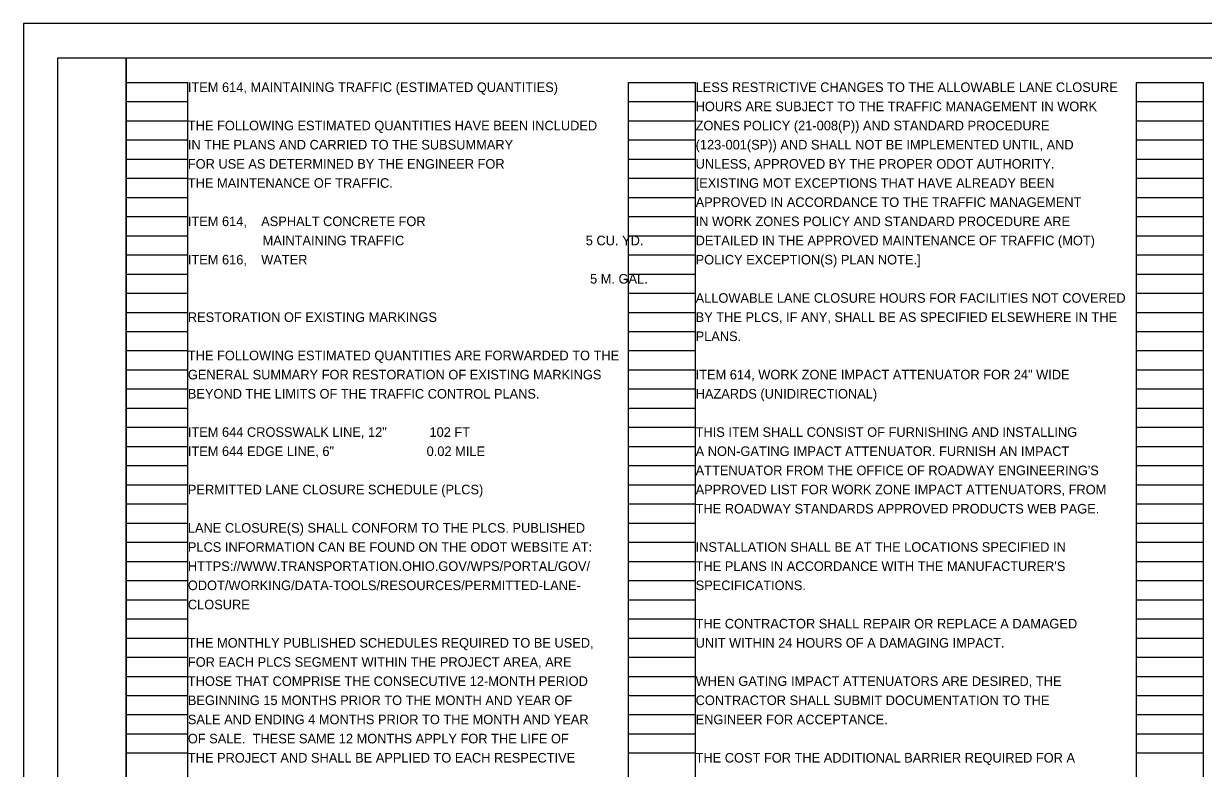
# Model space of a CAD drawing. Extents: x -49.3 to -15.3, y 0 to 22.
# Drawn here: x -49.3 to -32.06, y 11.11 to 22 of the extents above; entities that cross this region are included whole.
import ezdxf

# ---------------------------------------------------------------- set-up
doc = ezdxf.new("R2010")
doc.units = 0
for name, color, linetype in [('SC_Scratch1', 7, 'Continuous'), ('SC_Scratch2', 7, 'Continuous'), ('SH_Text', 7, 'Continuous')]:
    doc.layers.add(name, color=color, linetype=linetype)

msp = doc.modelspace()

# ---------------------------------------------------------------- linework, layer by layer
at = {"layer": 'SC_Scratch1'}
for p, q in [((-47.804, 0.98), (-47.804, 21.14)), ((-47.804, 21.14), (-46.904, 21.14)), ((-46.904, 0.98), (-46.904, 21.14)), ((-40.464, 0.98), (-40.464, 21.14)), ((-40.464, 21.14), (-39.484, 21.14)), ((-39.484, 0.98), (-39.484, 21.14)), ((-33.044, 0.98), (-33.044, 21.14)), ((-33.044, 21.14), (-32.064, 21.14)), ((-32.064, 0.98), (-32.064, 21.14)), ((-47.804, 20.86), (-46.904, 20.86)), ((-40.464, 20.86), (-39.484, 20.86)), ((-33.044, 20.86), (-32.064, 20.86)), ((-47.804, 20.58), (-46.904, 20.58)), ((-40.464, 20.58), (-39.484, 20.58)), ((-33.044, 20.58), (-32.064, 20.58)), ((-47.804, 20.3), (-46.904, 20.3)), ((-40.464, 20.3), (-39.484, 20.3)), ((-33.044, 20.3), (-32.064, 20.3)), ((-47.804, 20.02), (-46.904, 20.02)), ((-40.464, 20.02), (-39.484, 20.02)), ((-33.044, 20.02), (-32.064, 20.02)), ((-47.804, 19.74), (-46.904, 19.74)), ((-40.464, 19.74), (-39.484, 19.74)), ((-33.044, 19.74), (-32.064, 19.74)), ((-47.804, 19.46), (-46.904, 19.46)), ((-40.464, 19.46), (-39.484, 19.46)), ((-33.044, 19.46), (-32.064, 19.46)), ((-47.804, 19.18), (-46.904, 19.18)), ((-40.464, 19.18), (-39.484, 19.18)), ((-33.044, 19.18), (-32.064, 19.18)), ((-47.804, 18.9), (-46.904, 18.9)), ((-40.464, 18.9), (-39.484, 18.9)), ((-33.044, 18.9), (-32.064, 18.9)), ((-47.804, 18.62), (-46.904, 18.62)), ((-40.464, 18.62), (-39.484, 18.62)), ((-33.044, 18.62), (-32.064, 18.62)), ((-47.804, 18.34), (-46.904, 18.34)), ((-40.464, 18.34), (-39.484, 18.34)), ((-33.044, 18.34), (-32.064, 18.34)), ((-47.804, 18.06), (-46.904, 18.06)), ((-40.464, 18.06), (-39.484, 18.06)), ((-33.044, 18.06), (-32.064, 18.06)), ((-47.804, 17.78), (-46.904, 17.78)), ((-40.464, 17.78), (-39.484, 17.78)), ((-33.044, 17.78), (-32.064, 17.78)), ((-47.804, 17.5), (-46.904, 17.5)), ((-40.464, 17.5), (-39.484, 17.5)), ((-33.044, 17.5), (-32.064, 17.5)), ((-47.804, 17.22), (-46.904, 17.22)), ((-40.464, 17.22), (-39.484, 17.22)), ((-33.044, 17.22), (-32.064, 17.22)), ((-47.804, 16.94), (-46.904, 16.94)), ((-40.464, 16.94), (-39.484, 16.94)), ((-33.044, 16.94), (-32.064, 16.94)), ((-47.804, 16.66), (-46.904, 16.66)), ((-40.464, 16.66), (-39.484, 16.66)), ((-33.044, 16.66), (-32.064, 16.66)), ((-47.804, 16.38), (-46.904, 16.38)), ((-40.464, 16.38), (-39.484, 16.38)), ((-33.044, 16.38), (-32.064, 16.38)), ((-47.804, 16.1), (-46.904, 16.1)), ((-40.464, 16.1), (-39.484, 16.1)), ((-33.044, 16.1), (-32.064, 16.1)), ((-47.804, 15.82), (-46.904, 15.82)), ((-40.464, 15.82), (-39.484, 15.82)), ((-33.044, 15.82), (-32.064, 15.82)), ((-47.804, 15.54), (-46.904, 15.54)), ((-40.464, 15.54), (-39.484, 15.54)), ((-33.044, 15.54), (-32.064, 15.54)), ((-47.804, 15.26), (-46.904, 15.26)), ((-40.464, 15.26), (-39.484, 15.26)), ((-33.044, 15.26), (-32.064, 15.26)), ((-47.804, 14.98), (-46.904, 14.98)), ((-40.464, 14.98), (-39.484, 14.98)), ((-33.044, 14.98), (-32.064, 14.98)), ((-47.804, 14.7), (-46.904, 14.7)), ((-40.464, 14.7), (-39.484, 14.7)), ((-33.044, 14.7), (-32.064, 14.7)), ((-47.804, 14.42), (-46.904, 14.42)), ((-40.464, 14.42), (-39.484, 14.42)), ((-33.044, 14.42), (-32.064, 14.42)), ((-47.804, 14.14), (-46.904, 14.14)), ((-40.464, 14.14), (-39.484, 14.14)), ((-33.044, 14.14), (-32.064, 14.14)), ((-47.804, 13.86), (-46.904, 13.86)), ((-40.464, 13.86), (-39.484, 13.86)), ((-33.044, 13.86), (-32.064, 13.86)), ((-47.804, 13.58), (-46.904, 13.58)), ((-40.464, 13.58), (-39.484, 13.58)), ((-33.044, 13.58), (-32.064, 13.58)), ((-47.804, 13.3), (-46.904, 13.3)), ((-40.464, 13.3), (-39.484, 13.3)), ((-33.044, 13.3), (-32.064, 13.3)), ((-47.804, 13.02), (-46.904, 13.02)), ((-40.464, 13.02), (-39.484, 13.02)), ((-33.044, 13.02), (-32.064, 13.02)), ((-47.804, 12.74), (-46.904, 12.74)), ((-40.464, 12.74), (-39.484, 12.74)), ((-33.044, 12.74), (-32.064, 12.74)), ((-47.804, 12.46), (-46.904, 12.46)), ((-40.464, 12.46), (-39.484, 12.46)), ((-33.044, 12.46), (-32.064, 12.46)), ((-47.804, 12.18), (-46.904, 12.18)), ((-40.464, 12.18), (-39.484, 12.18)), ((-33.044, 12.18), (-32.064, 12.18)), ((-47.804, 11.9), (-46.904, 11.9)), ((-40.464, 11.9), (-39.484, 11.9)), ((-33.044, 11.9), (-32.064, 11.9)), ((-47.804, 11.62), (-46.904, 11.62)), ((-40.464, 11.62), (-39.484, 11.62)), ((-33.044, 11.62), (-32.064, 11.62)), ((-47.804, 11.34), (-46.904, 11.34)), ((-40.464, 11.34), (-39.484, 11.34)), ((-33.044, 11.34), (-32.064, 11.34))]:
    msp.add_line(p, q, dxfattribs=at)
at = {"layer": 'SC_Scratch2'}
for points in [[(-49.304, 0), (-15.304, 0), (-15.304, 22), (-49.304, 22)], [(-48.804, 21.5), (-47.804, 21.5), (-47.804, 0.5), (-48.804, 0.5)], [(-47.804, 21.5), (-15.804, 21.5), (-15.804, 0.5), (-47.804, 0.5)]]:
    msp.add_lwpolyline(points, close=True, dxfattribs=at)

# ---------------------------------------------------------------- texts
at = {"layer": 'SH_Text'}
for s, p in [('ITEM 614, MAINTAINING TRAFFIC (ESTIMATED QUANTITIES)', (-46.904, 21)), ('LESS RESTRICTIVE CHANGES TO THE ALLOWABLE LANE CLOSURE', (-39.484, 21)), ('HOURS ARE SUBJECT TO THE TRAFFIC MANAGEMENT IN WORK', (-39.484, 20.72)), ('THE FOLLOWING ESTIMATED QUANTITIES HAVE BEEN INCLUDED', (-46.904, 20.44)), ('ZONES POLICY (21-008(P)) AND STANDARD PROCEDURE', (-39.484, 20.44)), ('IN THE PLANS AND CARRIED TO THE SUBSUMMARY ', (-46.904, 20.16)), ('(123-001(SP)) AND SHALL NOT BE IMPLEMENTED UNTIL, AND', (-39.484, 20.16)), ('FOR USE AS DETERMINED BY THE ENGINEER FOR', (-46.904, 19.88)), ('UNLESS, APPROVED BY THE PROPER ODOT AUTHORITY.', (-39.484, 19.88)), ('THE MAINTENANCE OF TRAFFIC.', (-46.904, 19.6)), ('[EXISTING MOT EXCEPTIONS THAT HAVE ALREADY BEEN', (-39.484, 19.6)), ('APPROVED IN ACCORDANCE TO THE TRAFFIC MANAGEMENT', (-39.484, 19.32)), ('ITEM 614,    ASPHALT CONCRETE FOR', (-46.904, 19.04)), ('IN WORK ZONES POLICY AND STANDARD PROCEDURE ARE', (-39.484, 19.04)), ('                     MAINTAINING TRAFFIC                                                   5 CU. YD.', (-46.904, 18.76)), ('DETAILED IN THE APPROVED MAINTENANCE OF TRAFFIC (MOT)', (-39.484, 18.76)), ('ITEM 616,    WATER', (-46.904, 18.48)), ('POLICY EXCEPTION(S) PLAN NOTE.]', (-39.484, 18.48)), ('                                                                                                                 5 M. GAL.', (-46.904, 18.2)), ('ALLOWABLE LANE CLOSURE HOURS FOR FACILITIES NOT COVERED', (-39.484, 17.92)), ('RESTORATION OF EXISTING MARKINGS', (-46.904, 17.64)), ('BY THE PLCS, IF ANY, SHALL BE AS SPECIFIED ELSEWHERE IN THE', (-39.484, 17.64)), ('PLANS.', (-39.484, 17.36)), ('THE FOLLOWING ESTIMATED QUANTITIES ARE FORWARDED TO THE', (-46.904, 17.08)), ('GENERAL SUMMARY FOR RESTORATION OF EXISTING MARKINGS', (-46.904, 16.8)), ('ITEM 614, WORK ZONE IMPACT ATTENUATOR FOR 24" WIDE', (-39.484, 16.8)), ('BEYOND THE LIMITS OF THE TRAFFIC CONTROL PLANS.', (-46.904, 16.52)), ('HAZARDS (UNIDIRECTIONAL)', (-39.484, 16.52)), ('ITEM 644 CROSSWALK LINE, 12"            102 FT                ', (-46.904, 15.96)), ('THIS ITEM SHALL CONSIST OF FURNISHING AND INSTALLING', (-39.484, 15.96)), ('ITEM 644 EDGE LINE, 6"                          0.02 MILE', (-46.904, 15.68)), ('A NON-GATING IMPACT ATTENUATOR. FURNISH AN IMPACT', (-39.484, 15.68)), ("ATTENUATOR FROM THE OFFICE OF ROADWAY ENGINEERING'S", (-39.484, 15.4)), ('PERMITTED LANE CLOSURE SCHEDULE (PLCS)', (-46.904, 15.12)), ('APPROVED LIST FOR WORK ZONE IMPACT ATTENUATORS, FROM', (-39.484, 15.12)), ('THE ROADWAY STANDARDS APPROVED PRODUCTS WEB PAGE.', (-39.484, 14.84)), ('LANE CLOSURE(S) SHALL CONFORM TO THE PLCS. PUBLISHED', (-46.904, 14.56)), ('PLCS INFORMATION CAN BE FOUND ON THE ODOT WEBSITE AT:', (-46.904, 14.28)), ('INSTALLATION SHALL BE AT THE LOCATIONS SPECIFIED IN', (-39.484, 14.28)), ('HTTPS://WWW.TRANSPORTATION.OHIO.GOV/WPS/PORTAL/GOV/', (-46.904, 14)), ("THE PLANS IN ACCORDANCE WITH THE MANUFACTURER'S", (-39.484, 14)), ('ODOT/WORKING/DATA-TOOLS/RESOURCES/PERMITTED-LANE-', (-46.904, 13.72)), ('SPECIFICATIONS.', (-39.484, 13.72)), ('CLOSURE', (-46.904, 13.44)), ('THE CONTRACTOR SHALL REPAIR OR REPLACE A DAMAGED', (-39.484, 13.16)), ('THE MONTHLY PUBLISHED SCHEDULES REQUIRED TO BE USED,', (-46.904, 12.88)), ('UNIT WITHIN 24 HOURS OF A DAMAGING IMPACT.', (-39.484, 12.88)), ('FOR EACH PLCS SEGMENT WITHIN THE PROJECT AREA, ARE', (-46.904, 12.6)), ('THOSE THAT COMPRISE THE CONSECUTIVE 12-MONTH PERIOD', (-46.904, 12.32)), ('WHEN GATING IMPACT ATTENUATORS ARE DESIRED, THE', (-39.484, 12.32)), ('BEGINNING 15 MONTHS PRIOR TO THE MONTH AND YEAR OF', (-46.904, 12.04)), ('CONTRACTOR SHALL SUBMIT DOCUMENTATION TO THE', (-39.484, 12.04)), ('SALE AND ENDING 4 MONTHS PRIOR TO THE MONTH AND YEAR', (-46.904, 11.76)), ('ENGINEER FOR ACCEPTANCE.', (-39.484, 11.76)), ('OF SALE.  THESE SAME 12 MONTHS APPLY FOR THE LIFE OF', (-46.904, 11.48)), ('THE PROJECT AND SHALL BE APPLIED TO EACH RESPECTIVE', (-46.904, 11.2)), ('THE COST FOR THE ADDITIONAL BARRIER REQUIRED FOR A', (-39.484, 11.2))]:
    msp.add_text(s, height=0.14, dxfattribs=at).set_placement(p)

doc.saveas('drawing.dxf')
